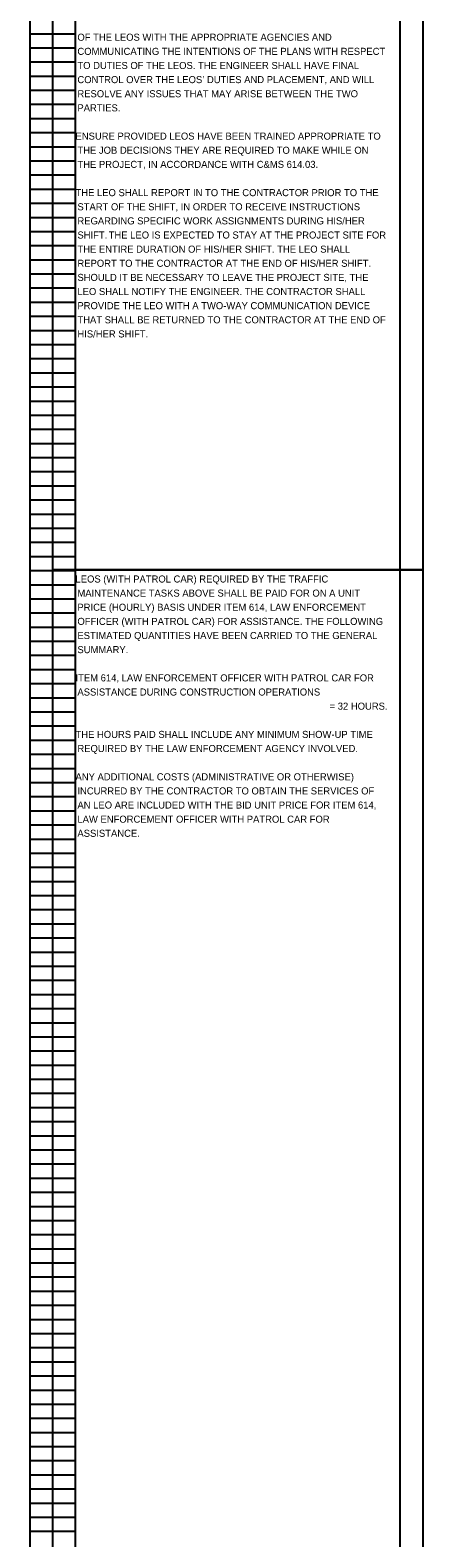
# Model space of a CAD drawing. Extents: x 0 to 19, y -301 to 22.
# Drawn here: x 1.5 to 9.29, y -139.15 to -109.27 of the extents above; entities that cross this region are included whole.
import ezdxf

# ---------------------------------------------------------------- set-up
doc = ezdxf.new("R2010")
doc.units = 0
doc.layers.add('SC_Scratch1', color=7, linetype='Continuous')
doc.layers.add('SH_Text', color=7, linetype='Continuous')

msp = doc.modelspace()

# ---------------------------------------------------------------- linework, layer by layer
at = {"layer": 'SC_Scratch1'}
for p, q in [((1.5, -119.98), (1.5, -99.82)), ((2.4, -119.98), (2.4, -99.82)), ((8.84, -119.98), (8.84, -99.82)), ((1.5, -109.34), (2.4, -109.34)), ((1.5, -109.62), (2.4, -109.62)), ((1.5, -109.9), (2.4, -109.9)), ((1.5, -110.18), (2.4, -110.18)), ((1.5, -110.46), (2.4, -110.46)), ((1.5, -110.74), (2.4, -110.74)), ((1.5, -111.02), (2.4, -111.02)), ((1.5, -111.3), (2.4, -111.3)), ((1.5, -111.58), (2.4, -111.58)), ((1.5, -111.86), (2.4, -111.86)), ((1.5, -112.14), (2.4, -112.14)), ((1.5, -112.42), (2.4, -112.42)), ((1.5, -112.7), (2.4, -112.7)), ((1.5, -112.98), (2.4, -112.98)), ((1.5, -113.26), (2.4, -113.26)), ((1.5, -113.54), (2.4, -113.54)), ((1.5, -113.82), (2.4, -113.82)), ((1.5, -114.1), (2.4, -114.1)), ((1.5, -114.38), (2.4, -114.38)), ((1.5, -114.66), (2.4, -114.66)), ((1.5, -114.94), (2.4, -114.94)), ((1.5, -115.22), (2.4, -115.22)), ((1.5, -115.5), (2.4, -115.5)), ((1.5, -115.78), (2.4, -115.78)), ((1.5, -116.06), (2.4, -116.06)), ((1.5, -116.34), (2.4, -116.34)), ((1.5, -116.62), (2.4, -116.62)), ((1.5, -116.9), (2.4, -116.9)), ((1.5, -117.18), (2.4, -117.18)), ((1.5, -117.46), (2.4, -117.46)), ((1.5, -117.74), (2.4, -117.74)), ((1.5, -118.02), (2.4, -118.02)), ((1.5, -118.3), (2.4, -118.3)), ((1.5, -118.58), (2.4, -118.58)), ((1.5, -118.86), (2.4, -118.86)), ((1.5, -119.14), (2.4, -119.14)), ((1.5, -119.42), (2.4, -119.42)), ((1.5, -119.7), (2.4, -119.7)), ((1.5, -119.98), (2.4, -119.98)), ((1.5, -119.98), (2.4, -119.98)), ((1.5, -140.14), (1.5, -119.98)), ((2.4, -140.14), (2.4, -119.98)), ((8.84, -140.14), (8.84, -119.98)), ((1.5, -120.26), (2.4, -120.26)), ((1.5, -120.54), (2.4, -120.54)), ((1.5, -120.82), (2.4, -120.82)), ((1.5, -121.1), (2.4, -121.1)), ((1.5, -121.38), (2.4, -121.38)), ((1.5, -121.66), (2.4, -121.66)), ((1.5, -121.94), (2.4, -121.94)), ((1.5, -122.22), (2.4, -122.22)), ((1.5, -122.5), (2.4, -122.5)), ((1.5, -122.78), (2.4, -122.78)), ((1.5, -123.06), (2.4, -123.06)), ((1.5, -123.34), (2.4, -123.34)), ((1.5, -123.62), (2.4, -123.62)), ((1.5, -123.9), (2.4, -123.9)), ((1.5, -124.18), (2.4, -124.18)), ((1.5, -124.46), (2.4, -124.46)), ((1.5, -124.74), (2.4, -124.74)), ((1.5, -125.02), (2.4, -125.02)), ((1.5, -125.3), (2.4, -125.3)), ((1.5, -125.58), (2.4, -125.58)), ((1.5, -125.86), (2.4, -125.86)), ((1.5, -126.14), (2.4, -126.14)), ((1.5, -126.42), (2.4, -126.42)), ((1.5, -126.7), (2.4, -126.7)), ((1.5, -126.98), (2.4, -126.98)), ((1.5, -127.26), (2.4, -127.26)), ((1.5, -127.54), (2.4, -127.54)), ((1.5, -127.82), (2.4, -127.82)), ((1.5, -128.1), (2.4, -128.1)), ((1.5, -128.38), (2.4, -128.38)), ((1.5, -128.66), (2.4, -128.66)), ((1.5, -128.94), (2.4, -128.94)), ((1.5, -129.22), (2.4, -129.22)), ((1.5, -129.5), (2.4, -129.5)), ((1.5, -129.78), (2.4, -129.78)), ((1.5, -130.06), (2.4, -130.06)), ((1.5, -130.34), (2.4, -130.34)), ((1.5, -130.62), (2.4, -130.62)), ((1.5, -130.9), (2.4, -130.9)), ((1.5, -131.18), (2.4, -131.18)), ((1.5, -131.46), (2.4, -131.46)), ((1.5, -131.74), (2.4, -131.74)), ((1.5, -132.02), (2.4, -132.02)), ((1.5, -132.3), (2.4, -132.3)), ((1.5, -132.58), (2.4, -132.58)), ((1.5, -132.86), (2.4, -132.86)), ((1.5, -133.14), (2.4, -133.14)), ((1.5, -133.42), (2.4, -133.42)), ((1.5, -133.7), (2.4, -133.7)), ((1.5, -133.98), (2.4, -133.98)), ((1.5, -134.26), (2.4, -134.26)), ((1.5, -134.54), (2.4, -134.54)), ((1.5, -134.82), (2.4, -134.82)), ((1.5, -135.1), (2.4, -135.1)), ((1.5, -135.38), (2.4, -135.38)), ((1.5, -135.66), (2.4, -135.66)), ((1.5, -135.94), (2.4, -135.94)), ((1.5, -136.22), (2.4, -136.22)), ((1.5, -136.5), (2.4, -136.5)), ((1.5, -136.78), (2.4, -136.78)), ((1.5, -137.06), (2.4, -137.06)), ((1.5, -137.34), (2.4, -137.34)), ((1.5, -137.62), (2.4, -137.62)), ((1.5, -137.9), (2.4, -137.9)), ((1.5, -138.18), (2.4, -138.18)), ((1.5, -138.46), (2.4, -138.46)), ((1.5, -138.74), (2.4, -138.74)), ((1.5, -139.02), (2.4, -139.02))]:
    msp.add_line(p, q, dxfattribs=at)
for points in [[(1.95, -99.803), (9.29, -99.803), (9.29, -119.963), (1.95, -119.963)], [(1.95, -119.963), (9.29, -119.963), (9.29, -140.123), (1.95, -140.123)]]:
    msp.add_lwpolyline(points, close=True, dxfattribs=at)

# ---------------------------------------------------------------- texts
at = {"layer": 'SH_Text'}
for s, p in [('OF THE LEOS WITH THE APPROPRIATE AGENCIES AND ', (2.438, -109.48)), ('COMMUNICATING THE INTENTIONS OF THE PLANS WITH RESPECT ', (2.438, -109.76)), ('TO DUTIES OF THE LEOS. THE ENGINEER SHALL HAVE FINAL ', (2.438, -110.04)), ('CONTROL OVER THE LEOS’ DUTIES AND PLACEMENT, AND WILL ', (2.438, -110.32)), ('RESOLVE ANY ISSUES THAT MAY ARISE BETWEEN THE TWO ', (2.438, -110.6)), ('PARTIES.', (2.438, -110.88)), ('ENSURE PROVIDED LEOS HAVE BEEN TRAINED APPROPRIATE TO ', (2.4, -111.44)), ('THE JOB DECISIONS THEY ARE REQUIRED TO MAKE WHILE ON ', (2.438, -111.72)), ('THE PROJECT, IN ACCORDANCE WITH C&MS 614.03.', (2.438, -112)), ('THE LEO SHALL REPORT IN TO THE CONTRACTOR PRIOR TO THE ', (2.4, -112.56)), ('START OF THE SHIFT, IN ORDER TO RECEIVE INSTRUCTIONS ', (2.438, -112.84)), ('REGARDING SPECIFIC WORK ASSIGNMENTS DURING HIS/HER ', (2.438, -113.12)), ('THE ENTIRE DURATION OF HIS/HER SHIFT. THE LEO SHALL ', (2.438, -113.68)), ('SHIFT.', (2.438, -113.4)), ('THE LEO IS EXPECTED TO STAY AT THE PROJECT SITE FOR ', (3.058, -113.4)), ('REPORT TO THE CONTRACTOR AT THE END OF HIS/HER SHIFT. ', (2.438, -113.96)), ('SHOULD IT BE NECESSARY TO LEAVE THE PROJECT SITE, THE ', (2.438, -114.24)), ('LEO SHALL NOTIFY THE ENGINEER. THE CONTRACTOR SHALL ', (2.438, -114.52)), ('PROVIDE THE LEO WITH A TWO-WAY COMMUNICATION DEVICE ', (2.438, -114.8)), ('THAT SHALL BE RETURNED TO THE CONTRACTOR AT THE END OF ', (2.438, -115.08)), ('HIS/HER SHIFT.', (2.438, -115.36)), ('LEOS (WITH PATROL CAR) REQUIRED BY THE TRAFFIC ', (2.4, -120.217)), ('MAINTENANCE TASKS ABOVE SHALL BE PAID FOR ON A UNIT ', (2.438, -120.497)), ('PRICE (HOURLY) BASIS UNDER ITEM 614, LAW ENFORCEMENT ', (2.438, -120.777)), ('OFFICER (WITH PATROL CAR) FOR ASSISTANCE. THE FOLLOWING ', (2.438, -121.057)), ('ESTIMATED QUANTITIES HAVE BEEN CARRIED TO THE GENERAL ', (2.438, -121.337)), ('SUMMARY.', (2.438, -121.617)), ('ITEM 614, LAW ENFORCEMENT OFFICER WITH PATROL CAR FOR ', (2.4, -122.177)), ('ASSISTANCE DURING CONSTRUCTION OPERATIONS', (2.438, -122.457)), ('= 32 HOURS.', (7.44, -122.737)), ('THE HOURS PAID SHALL INCLUDE ANY MINIMUM SHOW-UP TIME ', (2.4, -123.297)), ('REQUIRED BY THE LAW ENFORCEMENT AGENCY INVOLVED.', (2.438, -123.577)), ('ANY ADDITIONAL COSTS (ADMINISTRATIVE OR OTHERWISE) ', (2.4, -124.137)), ('INCURRED BY THE CONTRACTOR TO OBTAIN THE SERVICES OF ', (2.438, -124.417)), ('AN LEO ARE INCLUDED WITH THE BID UNIT PRICE FOR ITEM 614, ', (2.438, -124.697)), ('LAW ENFORCEMENT OFFICER WITH PATROL CAR FOR ', (2.438, -124.977)), ('ASSISTANCE.', (2.438, -125.257))]:
    msp.add_text(s, height=0.14, dxfattribs=at).set_placement(p)

doc.saveas('drawing.dxf')
